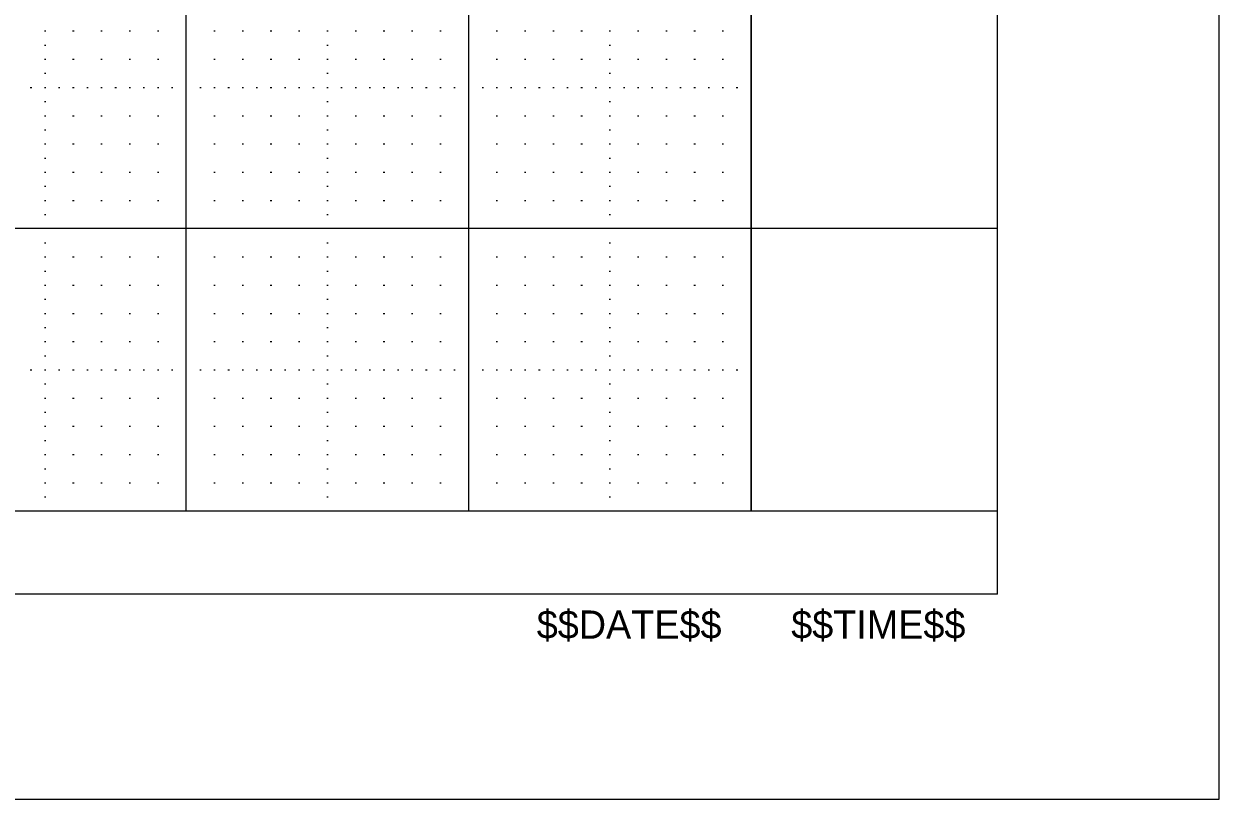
# Model space of a CAD drawing. Extents: x 0 to 34.3, y 0 to 22.
# Drawn here: x 29.768 to 34, y 0 to 2.745 of the extents above; entities that cross this region are included whole.
import ezdxf

# ---------------------------------------------------------------- set-up
doc = ezdxf.new("R2010")
doc.units = 0
for name, color, linetype in [('Level 1', 7, 'Continuous'), ('Level 4', 7, 'Continuous'), ('Level 48', 7, 'Continuous'), ('Level 5', 7, 'Continuous'), ('Level 63', 7, 'Continuous'), ('R_Border_Dark', 7, 'Continuous')]:
    doc.layers.add(name, color=color, linetype=linetype)

msp = doc.modelspace()

# ---------------------------------------------------------------- linework, layer by layer
at = {"layer": 'Level 1'}
for q in [(33.215, 21.272), (1.597, 0.726)]:
    msp.add_line((33.215, 0.726), q, dxfattribs=at)
msp.add_lwpolyline([(2.343, 9.02), (32.343, 9.02), (32.343, 1.02), (2.343, 1.02)], close=True, dxfattribs=at)
at = {"layer": 'Level 4'}
msp.add_line((33.215, 1.02), (1.597, 1.02), dxfattribs=at)
at = {"layer": 'Level 5'}
for p, q in [((29.8405, 2.72), (29.8455, 2.72)), ((29.9405, 2.72), (29.9455, 2.72)), ((30.0405, 2.72), (30.0455, 2.72)), ((30.1405, 2.72), (30.1455, 2.72)), ((30.2405, 2.72), (30.2455, 2.72)), ((30.4405, 2.72), (30.4455, 2.72)), ((30.5405, 2.72), (30.5455, 2.72)), ((30.6405, 2.72), (30.6455, 2.72)), ((30.7405, 2.72), (30.7455, 2.72)), ((30.8405, 2.72), (30.8455, 2.72)), ((30.9405, 2.72), (30.9455, 2.72)), ((31.0405, 2.72), (31.0455, 2.72)), ((31.1405, 2.72), (31.1455, 2.72)), ((31.2405, 2.72), (31.2455, 2.72)), ((31.4405, 2.72), (31.4455, 2.72)), ((31.5405, 2.72), (31.5455, 2.72)), ((31.6405, 2.72), (31.6455, 2.72)), ((31.7405, 2.72), (31.7455, 2.72)), ((31.8405, 2.72), (31.8455, 2.72)), ((31.9405, 2.72), (31.9455, 2.72)), ((32.0405, 2.72), (32.0455, 2.72)), ((32.1405, 2.72), (32.1455, 2.72)), ((32.2405, 2.72), (32.2455, 2.72)), ((29.8405, 2.67), (29.8455, 2.67)), ((30.8405, 2.67), (30.8455, 2.67)), ((31.8405, 2.67), (31.8455, 2.67)), ((29.8405, 2.62), (29.8455, 2.62)), ((29.9405, 2.62), (29.9455, 2.62)), ((30.0405, 2.62), (30.0455, 2.62)), ((30.1405, 2.62), (30.1455, 2.62)), ((30.2405, 2.62), (30.2455, 2.62)), ((30.4405, 2.62), (30.4455, 2.62)), ((30.5405, 2.62), (30.5455, 2.62)), ((30.6405, 2.62), (30.6455, 2.62)), ((30.7405, 2.62), (30.7455, 2.62)), ((30.8405, 2.62), (30.8455, 2.62)), ((30.9405, 2.62), (30.9455, 2.62)), ((31.0405, 2.62), (31.0455, 2.62)), ((31.1405, 2.62), (31.1455, 2.62)), ((31.2405, 2.62), (31.2455, 2.62)), ((31.4405, 2.62), (31.4455, 2.62)), ((31.5405, 2.62), (31.5455, 2.62)), ((31.6405, 2.62), (31.6455, 2.62)), ((31.7405, 2.62), (31.7455, 2.62)), ((31.8405, 2.62), (31.8455, 2.62)), ((31.9405, 2.62), (31.9455, 2.62)), ((32.0405, 2.62), (32.0455, 2.62)), ((32.1405, 2.62), (32.1455, 2.62)), ((32.2405, 2.62), (32.2455, 2.62)), ((29.8405, 2.57), (29.8455, 2.57)), ((30.8405, 2.57), (30.8455, 2.57)), ((31.8405, 2.57), (31.8455, 2.57)), ((29.7905, 2.52), (29.7955, 2.52)), ((29.8405, 2.52), (29.8455, 2.52)), ((29.8905, 2.52), (29.8955, 2.52)), ((29.9405, 2.52), (29.9455, 2.52)), ((29.9905, 2.52), (29.9955, 2.52)), ((30.0405, 2.52), (30.0455, 2.52)), ((30.0905, 2.52), (30.0955, 2.52)), ((30.1405, 2.52), (30.1455, 2.52)), ((30.1905, 2.52), (30.1955, 2.52)), ((30.2405, 2.52), (30.2455, 2.52)), ((30.2905, 2.52), (30.2955, 2.52)), ((30.3905, 2.52), (30.3955, 2.52)), ((30.4405, 2.52), (30.4455, 2.52)), ((30.4905, 2.52), (30.4955, 2.52)), ((30.5405, 2.52), (30.5455, 2.52)), ((30.5905, 2.52), (30.5955, 2.52)), ((30.6405, 2.52), (30.6455, 2.52)), ((30.6905, 2.52), (30.6955, 2.52)), ((30.7405, 2.52), (30.7455, 2.52)), ((30.7905, 2.52), (30.7955, 2.52)), ((30.8405, 2.52), (30.8455, 2.52)), ((30.8905, 2.52), (30.8955, 2.52)), ((30.9405, 2.52), (30.9455, 2.52)), ((30.9905, 2.52), (30.9955, 2.52)), ((31.0405, 2.52), (31.0455, 2.52)), ((31.0905, 2.52), (31.0955, 2.52)), ((31.1405, 2.52), (31.1455, 2.52)), ((31.1905, 2.52), (31.1955, 2.52)), ((31.2405, 2.52), (31.2455, 2.52)), ((31.2905, 2.52), (31.2955, 2.52)), ((31.3905, 2.52), (31.3955, 2.52)), ((31.4405, 2.52), (31.4455, 2.52)), ((31.4905, 2.52), (31.4955, 2.52)), ((31.5405, 2.52), (31.5455, 2.52)), ((31.5905, 2.52), (31.5955, 2.52)), ((31.6405, 2.52), (31.6455, 2.52)), ((31.6905, 2.52), (31.6955, 2.52)), ((31.7405, 2.52), (31.7455, 2.52)), ((31.7905, 2.52), (31.7955, 2.52)), ((31.8405, 2.52), (31.8455, 2.52)), ((31.8905, 2.52), (31.8955, 2.52)), ((31.9405, 2.52), (31.9455, 2.52)), ((31.9905, 2.52), (31.9955, 2.52)), ((32.0405, 2.52), (32.0455, 2.52)), ((32.0905, 2.52), (32.0955, 2.52)), ((32.1405, 2.52), (32.1455, 2.52)), ((32.1905, 2.52), (32.1955, 2.52)), ((32.2405, 2.52), (32.2455, 2.52)), ((32.2905, 2.52), (32.2955, 2.52)), ((29.8405, 2.47), (29.8455, 2.47)), ((30.8405, 2.47), (30.8455, 2.47)), ((31.8405, 2.47), (31.8455, 2.47)), ((29.8405, 2.42), (29.8455, 2.42)), ((29.9405, 2.42), (29.9455, 2.42)), ((30.0405, 2.42), (30.0455, 2.42)), ((30.1405, 2.42), (30.1455, 2.42)), ((30.2405, 2.42), (30.2455, 2.42)), ((30.4405, 2.42), (30.4455, 2.42)), ((30.5405, 2.42), (30.5455, 2.42)), ((30.6405, 2.42), (30.6455, 2.42)), ((30.7405, 2.42), (30.7455, 2.42)), ((30.8405, 2.42), (30.8455, 2.42)), ((30.9405, 2.42), (30.9455, 2.42)), ((31.0405, 2.42), (31.0455, 2.42)), ((31.1405, 2.42), (31.1455, 2.42)), ((31.2405, 2.42), (31.2455, 2.42)), ((31.4405, 2.42), (31.4455, 2.42)), ((31.5405, 2.42), (31.5455, 2.42)), ((31.6405, 2.42), (31.6455, 2.42)), ((31.7405, 2.42), (31.7455, 2.42)), ((31.8405, 2.42), (31.8455, 2.42)), ((31.9405, 2.42), (31.9455, 2.42)), ((32.0405, 2.42), (32.0455, 2.42)), ((32.1405, 2.42), (32.1455, 2.42)), ((32.2405, 2.42), (32.2455, 2.42)), ((29.8405, 2.37), (29.8455, 2.37)), ((30.8405, 2.37), (30.8455, 2.37)), ((31.8405, 2.37), (31.8455, 2.37)), ((29.8405, 2.32), (29.8455, 2.32)), ((29.9405, 2.32), (29.9455, 2.32)), ((30.0405, 2.32), (30.0455, 2.32)), ((30.1405, 2.32), (30.1455, 2.32)), ((30.2405, 2.32), (30.2455, 2.32)), ((30.4405, 2.32), (30.4455, 2.32)), ((30.5405, 2.32), (30.5455, 2.32)), ((30.6405, 2.32), (30.6455, 2.32)), ((30.7405, 2.32), (30.7455, 2.32)), ((30.8405, 2.32), (30.8455, 2.32)), ((30.9405, 2.32), (30.9455, 2.32)), ((31.0405, 2.32), (31.0455, 2.32)), ((31.1405, 2.32), (31.1455, 2.32)), ((31.2405, 2.32), (31.2455, 2.32)), ((31.4405, 2.32), (31.4455, 2.32)), ((31.5405, 2.32), (31.5455, 2.32)), ((31.6405, 2.32), (31.6455, 2.32)), ((31.7405, 2.32), (31.7455, 2.32)), ((31.8405, 2.32), (31.8455, 2.32)), ((31.9405, 2.32), (31.9455, 2.32)), ((32.0405, 2.32), (32.0455, 2.32)), ((32.1405, 2.32), (32.1455, 2.32)), ((32.2405, 2.32), (32.2455, 2.32)), ((29.8405, 2.27), (29.8455, 2.27)), ((30.8405, 2.27), (30.8455, 2.27)), ((31.8405, 2.27), (31.8455, 2.27)), ((29.8405, 2.22), (29.8455, 2.22)), ((29.9405, 2.22), (29.9455, 2.22)), ((30.0405, 2.22), (30.0455, 2.22)), ((30.1405, 2.22), (30.1455, 2.22)), ((30.2405, 2.22), (30.2455, 2.22)), ((30.4405, 2.22), (30.4455, 2.22)), ((30.5405, 2.22), (30.5455, 2.22)), ((30.6405, 2.22), (30.6455, 2.22)), ((30.7405, 2.22), (30.7455, 2.22)), ((30.8405, 2.22), (30.8455, 2.22)), ((30.9405, 2.22), (30.9455, 2.22)), ((31.0405, 2.22), (31.0455, 2.22)), ((31.1405, 2.22), (31.1455, 2.22)), ((31.2405, 2.22), (31.2455, 2.22)), ((31.4405, 2.22), (31.4455, 2.22)), ((31.5405, 2.22), (31.5455, 2.22)), ((31.6405, 2.22), (31.6455, 2.22)), ((31.7405, 2.22), (31.7455, 2.22)), ((31.8405, 2.22), (31.8455, 2.22)), ((31.9405, 2.22), (31.9455, 2.22)), ((32.0405, 2.22), (32.0455, 2.22)), ((32.1405, 2.22), (32.1455, 2.22)), ((32.2405, 2.22), (32.2455, 2.22)), ((29.8405, 2.17), (29.8455, 2.17)), ((30.8405, 2.17), (30.8455, 2.17)), ((31.8405, 2.17), (31.8455, 2.17)), ((29.8405, 2.12), (29.8455, 2.12)), ((29.9405, 2.12), (29.9455, 2.12)), ((30.0405, 2.12), (30.0455, 2.12)), ((30.1405, 2.12), (30.1455, 2.12)), ((30.2405, 2.12), (30.2455, 2.12)), ((30.4405, 2.12), (30.4455, 2.12)), ((30.5405, 2.12), (30.5455, 2.12)), ((30.6405, 2.12), (30.6455, 2.12)), ((30.7405, 2.12), (30.7455, 2.12)), ((30.8405, 2.12), (30.8455, 2.12)), ((30.9405, 2.12), (30.9455, 2.12)), ((31.0405, 2.12), (31.0455, 2.12)), ((31.1405, 2.12), (31.1455, 2.12)), ((31.2405, 2.12), (31.2455, 2.12)), ((31.4405, 2.12), (31.4455, 2.12)), ((31.5405, 2.12), (31.5455, 2.12)), ((31.6405, 2.12), (31.6455, 2.12)), ((31.7405, 2.12), (31.7455, 2.12)), ((31.8405, 2.12), (31.8455, 2.12)), ((31.9405, 2.12), (31.9455, 2.12)), ((32.0405, 2.12), (32.0455, 2.12)), ((32.1405, 2.12), (32.1455, 2.12)), ((32.2405, 2.12), (32.2455, 2.12)), ((29.8405, 2.07), (29.8455, 2.07)), ((30.8405, 2.07), (30.8455, 2.07)), ((31.8405, 2.07), (31.8455, 2.07)), ((29.8405, 1.97), (29.8455, 1.97)), ((30.8405, 1.97), (30.8455, 1.97)), ((31.8405, 1.97), (31.8455, 1.97)), ((29.8405, 1.92), (29.8455, 1.92)), ((29.9405, 1.92), (29.9455, 1.92)), ((30.0405, 1.92), (30.0455, 1.92)), ((30.1405, 1.92), (30.1455, 1.92)), ((30.2405, 1.92), (30.2455, 1.92)), ((30.4405, 1.92), (30.4455, 1.92)), ((30.5405, 1.92), (30.5455, 1.92)), ((30.6405, 1.92), (30.6455, 1.92)), ((30.7405, 1.92), (30.7455, 1.92)), ((30.8405, 1.92), (30.8455, 1.92)), ((30.9405, 1.92), (30.9455, 1.92)), ((31.0405, 1.92), (31.0455, 1.92)), ((31.1405, 1.92), (31.1455, 1.92)), ((31.2405, 1.92), (31.2455, 1.92)), ((31.4405, 1.92), (31.4455, 1.92)), ((31.5405, 1.92), (31.5455, 1.92)), ((31.6405, 1.92), (31.6455, 1.92)), ((31.7405, 1.92), (31.7455, 1.92)), ((31.8405, 1.92), (31.8455, 1.92)), ((31.9405, 1.92), (31.9455, 1.92)), ((32.0405, 1.92), (32.0455, 1.92)), ((32.1405, 1.92), (32.1455, 1.92)), ((32.2405, 1.92), (32.2455, 1.92)), ((29.8405, 1.87), (29.8455, 1.87)), ((30.8405, 1.87), (30.8455, 1.87)), ((31.8405, 1.87), (31.8455, 1.87)), ((29.8405, 1.82), (29.8455, 1.82)), ((29.9405, 1.82), (29.9455, 1.82)), ((30.0405, 1.82), (30.0455, 1.82)), ((30.1405, 1.82), (30.1455, 1.82)), ((30.2405, 1.82), (30.2455, 1.82)), ((30.4405, 1.82), (30.4455, 1.82)), ((30.5405, 1.82), (30.5455, 1.82)), ((30.6405, 1.82), (30.6455, 1.82)), ((30.7405, 1.82), (30.7455, 1.82)), ((30.8405, 1.82), (30.8455, 1.82)), ((30.9405, 1.82), (30.9455, 1.82)), ((31.0405, 1.82), (31.0455, 1.82)), ((31.1405, 1.82), (31.1455, 1.82)), ((31.2405, 1.82), (31.2455, 1.82)), ((31.4405, 1.82), (31.4455, 1.82)), ((31.5405, 1.82), (31.5455, 1.82)), ((31.6405, 1.82), (31.6455, 1.82)), ((31.7405, 1.82), (31.7455, 1.82)), ((31.8405, 1.82), (31.8455, 1.82)), ((31.9405, 1.82), (31.9455, 1.82)), ((32.0405, 1.82), (32.0455, 1.82)), ((32.1405, 1.82), (32.1455, 1.82)), ((32.2405, 1.82), (32.2455, 1.82)), ((29.8405, 1.77), (29.8455, 1.77)), ((30.8405, 1.77), (30.8455, 1.77)), ((31.8405, 1.77), (31.8455, 1.77)), ((29.8405, 1.72), (29.8455, 1.72)), ((29.9405, 1.72), (29.9455, 1.72)), ((30.0405, 1.72), (30.0455, 1.72)), ((30.1405, 1.72), (30.1455, 1.72)), ((30.2405, 1.72), (30.2455, 1.72)), ((30.4405, 1.72), (30.4455, 1.72)), ((30.5405, 1.72), (30.5455, 1.72)), ((30.6405, 1.72), (30.6455, 1.72)), ((30.7405, 1.72), (30.7455, 1.72)), ((30.8405, 1.72), (30.8455, 1.72)), ((30.9405, 1.72), (30.9455, 1.72)), ((31.0405, 1.72), (31.0455, 1.72)), ((31.1405, 1.72), (31.1455, 1.72)), ((31.2405, 1.72), (31.2455, 1.72)), ((31.4405, 1.72), (31.4455, 1.72)), ((31.5405, 1.72), (31.5455, 1.72)), ((31.6405, 1.72), (31.6455, 1.72)), ((31.7405, 1.72), (31.7455, 1.72)), ((31.8405, 1.72), (31.8455, 1.72)), ((31.9405, 1.72), (31.9455, 1.72)), ((32.0405, 1.72), (32.0455, 1.72)), ((32.1405, 1.72), (32.1455, 1.72)), ((32.2405, 1.72), (32.2455, 1.72)), ((29.8405, 1.67), (29.8455, 1.67)), ((30.8405, 1.67), (30.8455, 1.67)), ((31.8405, 1.67), (31.8455, 1.67)), ((29.8405, 1.62), (29.8455, 1.62)), ((29.9405, 1.62), (29.9455, 1.62)), ((30.0405, 1.62), (30.0455, 1.62)), ((30.1405, 1.62), (30.1455, 1.62)), ((30.2405, 1.62), (30.2455, 1.62)), ((30.4405, 1.62), (30.4455, 1.62)), ((30.5405, 1.62), (30.5455, 1.62)), ((30.6405, 1.62), (30.6455, 1.62)), ((30.7405, 1.62), (30.7455, 1.62)), ((30.8405, 1.62), (30.8455, 1.62)), ((30.9405, 1.62), (30.9455, 1.62)), ((31.0405, 1.62), (31.0455, 1.62)), ((31.1405, 1.62), (31.1455, 1.62)), ((31.2405, 1.62), (31.2455, 1.62)), ((31.4405, 1.62), (31.4455, 1.62)), ((31.5405, 1.62), (31.5455, 1.62)), ((31.6405, 1.62), (31.6455, 1.62)), ((31.7405, 1.62), (31.7455, 1.62)), ((31.8405, 1.62), (31.8455, 1.62)), ((31.9405, 1.62), (31.9455, 1.62)), ((32.0405, 1.62), (32.0455, 1.62)), ((32.1405, 1.62), (32.1455, 1.62)), ((32.2405, 1.62), (32.2455, 1.62)), ((29.8405, 1.57), (29.8455, 1.57)), ((30.8405, 1.57), (30.8455, 1.57)), ((31.8405, 1.57), (31.8455, 1.57)), ((29.7905, 1.52), (29.7955, 1.52)), ((29.8405, 1.52), (29.8455, 1.52)), ((29.8905, 1.52), (29.8955, 1.52)), ((29.9405, 1.52), (29.9455, 1.52)), ((29.9905, 1.52), (29.9955, 1.52)), ((30.0405, 1.52), (30.0455, 1.52)), ((30.0905, 1.52), (30.0955, 1.52)), ((30.1405, 1.52), (30.1455, 1.52)), ((30.1905, 1.52), (30.1955, 1.52)), ((30.2405, 1.52), (30.2455, 1.52)), ((30.2905, 1.52), (30.2955, 1.52)), ((30.3905, 1.52), (30.3955, 1.52)), ((30.4405, 1.52), (30.4455, 1.52)), ((30.4905, 1.52), (30.4955, 1.52)), ((30.5405, 1.52), (30.5455, 1.52)), ((30.5905, 1.52), (30.5955, 1.52)), ((30.6405, 1.52), (30.6455, 1.52)), ((30.6905, 1.52), (30.6955, 1.52)), ((30.7405, 1.52), (30.7455, 1.52)), ((30.7905, 1.52), (30.7955, 1.52)), ((30.8405, 1.52), (30.8455, 1.52)), ((30.8905, 1.52), (30.8955, 1.52)), ((30.9405, 1.52), (30.9455, 1.52)), ((30.9905, 1.52), (30.9955, 1.52)), ((31.0405, 1.52), (31.0455, 1.52)), ((31.0905, 1.52), (31.0955, 1.52)), ((31.1405, 1.52), (31.1455, 1.52)), ((31.1905, 1.52), (31.1955, 1.52)), ((31.2405, 1.52), (31.2455, 1.52)), ((31.2905, 1.52), (31.2955, 1.52)), ((31.3905, 1.52), (31.3955, 1.52)), ((31.4405, 1.52), (31.4455, 1.52)), ((31.4905, 1.52), (31.4955, 1.52)), ((31.5405, 1.52), (31.5455, 1.52)), ((31.5905, 1.52), (31.5955, 1.52)), ((31.6405, 1.52), (31.6455, 1.52)), ((31.6905, 1.52), (31.6955, 1.52)), ((31.7405, 1.52), (31.7455, 1.52)), ((31.7905, 1.52), (31.7955, 1.52)), ((31.8405, 1.52), (31.8455, 1.52)), ((31.8905, 1.52), (31.8955, 1.52)), ((31.9405, 1.52), (31.9455, 1.52)), ((31.9905, 1.52), (31.9955, 1.52)), ((32.0405, 1.52), (32.0455, 1.52)), ((32.0905, 1.52), (32.0955, 1.52)), ((32.1405, 1.52), (32.1455, 1.52)), ((32.1905, 1.52), (32.1955, 1.52)), ((32.2405, 1.52), (32.2455, 1.52)), ((32.2905, 1.52), (32.2955, 1.52)), ((29.8405, 1.47), (29.8455, 1.47)), ((30.8405, 1.47), (30.8455, 1.47)), ((31.8405, 1.47), (31.8455, 1.47)), ((29.8405, 1.42), (29.8455, 1.42)), ((29.9405, 1.42), (29.9455, 1.42)), ((30.0405, 1.42), (30.0455, 1.42)), ((30.1405, 1.42), (30.1455, 1.42)), ((30.2405, 1.42), (30.2455, 1.42)), ((30.4405, 1.42), (30.4455, 1.42)), ((30.5405, 1.42), (30.5455, 1.42)), ((30.6405, 1.42), (30.6455, 1.42)), ((30.7405, 1.42), (30.7455, 1.42)), ((30.8405, 1.42), (30.8455, 1.42)), ((30.9405, 1.42), (30.9455, 1.42)), ((31.0405, 1.42), (31.0455, 1.42)), ((31.1405, 1.42), (31.1455, 1.42)), ((31.2405, 1.42), (31.2455, 1.42)), ((31.4405, 1.42), (31.4455, 1.42)), ((31.5405, 1.42), (31.5455, 1.42)), ((31.6405, 1.42), (31.6455, 1.42)), ((31.7405, 1.42), (31.7455, 1.42)), ((31.8405, 1.42), (31.8455, 1.42)), ((31.9405, 1.42), (31.9455, 1.42)), ((32.0405, 1.42), (32.0455, 1.42)), ((32.1405, 1.42), (32.1455, 1.42)), ((32.2405, 1.42), (32.2455, 1.42)), ((29.8405, 1.37), (29.8455, 1.37)), ((30.8405, 1.37), (30.8455, 1.37)), ((31.8405, 1.37), (31.8455, 1.37)), ((29.8405, 1.32), (29.8455, 1.32)), ((29.9405, 1.32), (29.9455, 1.32)), ((30.0405, 1.32), (30.0455, 1.32)), ((30.1405, 1.32), (30.1455, 1.32)), ((30.2405, 1.32), (30.2455, 1.32)), ((30.4405, 1.32), (30.4455, 1.32)), ((30.5405, 1.32), (30.5455, 1.32)), ((30.6405, 1.32), (30.6455, 1.32)), ((30.7405, 1.32), (30.7455, 1.32)), ((30.8405, 1.32), (30.8455, 1.32)), ((30.9405, 1.32), (30.9455, 1.32)), ((31.0405, 1.32), (31.0455, 1.32)), ((31.1405, 1.32), (31.1455, 1.32)), ((31.2405, 1.32), (31.2455, 1.32)), ((31.4405, 1.32), (31.4455, 1.32)), ((31.5405, 1.32), (31.5455, 1.32)), ((31.6405, 1.32), (31.6455, 1.32)), ((31.7405, 1.32), (31.7455, 1.32)), ((31.8405, 1.32), (31.8455, 1.32)), ((31.9405, 1.32), (31.9455, 1.32)), ((32.0405, 1.32), (32.0455, 1.32)), ((32.1405, 1.32), (32.1455, 1.32)), ((32.2405, 1.32), (32.2455, 1.32)), ((29.8405, 1.27), (29.8455, 1.27)), ((30.8405, 1.27), (30.8455, 1.27)), ((31.8405, 1.27), (31.8455, 1.27)), ((29.8405, 1.22), (29.8455, 1.22)), ((29.9405, 1.22), (29.9455, 1.22)), ((30.0405, 1.22), (30.0455, 1.22)), ((30.1405, 1.22), (30.1455, 1.22)), ((30.2405, 1.22), (30.2455, 1.22)), ((30.4405, 1.22), (30.4455, 1.22)), ((30.5405, 1.22), (30.5455, 1.22)), ((30.6405, 1.22), (30.6455, 1.22)), ((30.7405, 1.22), (30.7455, 1.22)), ((30.8405, 1.22), (30.8455, 1.22)), ((30.9405, 1.22), (30.9455, 1.22)), ((31.0405, 1.22), (31.0455, 1.22)), ((31.1405, 1.22), (31.1455, 1.22)), ((31.2405, 1.22), (31.2455, 1.22)), ((31.4405, 1.22), (31.4455, 1.22)), ((31.5405, 1.22), (31.5455, 1.22)), ((31.6405, 1.22), (31.6455, 1.22)), ((31.7405, 1.22), (31.7455, 1.22)), ((31.8405, 1.22), (31.8455, 1.22)), ((31.9405, 1.22), (31.9455, 1.22)), ((32.0405, 1.22), (32.0455, 1.22)), ((32.1405, 1.22), (32.1455, 1.22)), ((32.2405, 1.22), (32.2455, 1.22)), ((29.8405, 1.17), (29.8455, 1.17)), ((30.8405, 1.17), (30.8455, 1.17)), ((31.8405, 1.17), (31.8455, 1.17)), ((29.8405, 1.12), (29.8455, 1.12)), ((29.9405, 1.12), (29.9455, 1.12)), ((30.0405, 1.12), (30.0455, 1.12)), ((30.1405, 1.12), (30.1455, 1.12)), ((30.2405, 1.12), (30.2455, 1.12)), ((30.4405, 1.12), (30.4455, 1.12)), ((30.5405, 1.12), (30.5455, 1.12)), ((30.6405, 1.12), (30.6455, 1.12)), ((30.7405, 1.12), (30.7455, 1.12)), ((30.8405, 1.12), (30.8455, 1.12)), ((30.9405, 1.12), (30.9455, 1.12)), ((31.0405, 1.12), (31.0455, 1.12)), ((31.1405, 1.12), (31.1455, 1.12)), ((31.2405, 1.12), (31.2455, 1.12)), ((31.4405, 1.12), (31.4455, 1.12)), ((31.5405, 1.12), (31.5455, 1.12)), ((31.6405, 1.12), (31.6455, 1.12)), ((31.7405, 1.12), (31.7455, 1.12)), ((31.8405, 1.12), (31.8455, 1.12)), ((31.9405, 1.12), (31.9455, 1.12)), ((32.0405, 1.12), (32.0455, 1.12)), ((32.1405, 1.12), (32.1455, 1.12)), ((32.2405, 1.12), (32.2455, 1.12)), ((29.8405, 1.07), (29.8455, 1.07)), ((30.8405, 1.07), (30.8455, 1.07)), ((31.8405, 1.07), (31.8455, 1.07))]:
    msp.add_line(p, q, dxfattribs=at)
at = {"layer": 'Level 63'}
msp.add_lwpolyline([(0, 0), (34, 0), (34, 22), (0, 22)], close=True, dxfattribs=at)
msp.add_lwpolyline([(32.343, 9.02), (32.343, 1.02), (2.343, 1.02), (2.343, 9.02)], dxfattribs=at)
at = {"layer": 'R_Border_Dark'}
for p, q in [((30.343, 1.02), (30.343, 9.02)), ((31.343, 1.02), (31.343, 9.02)), ((32.343, 1.02), (32.343, 9.02)), ((33.215, 2.02), (1.597, 2.02))]:
    msp.add_line(p, q, dxfattribs=at)
msp.add_lwpolyline([(32.343, 9.02), (32.343, 1.02), (2.343, 1.02), (2.343, 9.02)], dxfattribs=at)

# ---------------------------------------------------------------- texts
at = {"layer": 'Level 48'}
for s, p in [('$$DATE$$', (31.584, 0.568)), ('$$TIME$$', (32.485, 0.568))]:
    msp.add_text(s, height=0.1, dxfattribs=at).set_placement(p)

doc.saveas('drawing.dxf')
